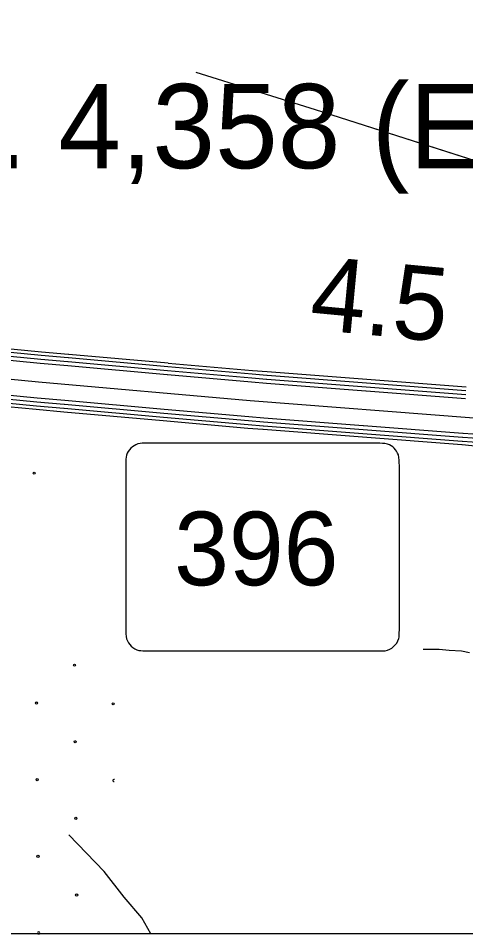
# Model space of a CAD drawing. Extents: x 1577619 to 1828281, y 483481 to 598136.
# Drawn here: x 1689672 to 1691916, y 508120 to 512713 of the extents above; entities that cross this region are included whole.
import ezdxf

# ---------------------------------------------------------------- set-up
doc = ezdxf.new("R2010")
doc.units = 0
for name, color, linetype in [('DESIGN - EROSION CONTROL - Devices', 7, 'Continuous'), ('DESIGN - ROW - Slope Lines', 7, 'Continuous'), ('DESIGN - SHEET - Linework', 7, 'Continuous'), ('DESIGN - TRAFFIC CONTROL PERMANENT - Signalization', 7, 'Continuous'), ('DESIGN - TRANSPORTATION - Text', 7, 'Continuous'), ('SURVEY - CENTERLINE - Preliminary Text', 7, 'Continuous'), ('SURVEY - DRAINAGE - Natural Features', 7, 'Continuous'), ('SURVEY - VEGETATION - Features with Text', 7, 'Continuous')]:
    doc.layers.add(name, color=color, linetype=linetype)

msp = doc.modelspace()

# ---------------------------------------------------------------- linework, layer by layer
at = {"layer": 'DESIGN - EROSION CONTROL - Devices'}
msp.add_line((1689770.1, 508119.9), (1689777.7, 508119.9), dxfattribs=at)
for centre in [(1689751.5, 510430.9), (1689953.1, 509467.7), (1689762.7, 509277.3), (1690147.3, 509273.5), (1689956.8, 509083.1), (1689766.4, 508892.7), (1689960.6, 508698.6), (1689770.2, 508508.2), (1689964.3, 508314)]:
    msp.add_circle(centre, 5.28, dxfattribs=at)
for centre, start, end in [((1690151, 508889), 61.0095, 287.6299), ((1689773.9, 508123.6), 315.4751, 224.5249)]:
    msp.add_arc(centre, 5.28, start, end, dxfattribs=at)
at = {"layer": 'DESIGN - ROW - Slope Lines'}
for p, q in [((1691472.6, 510580.9), (1690315.7, 510580.8)), ((1690210.5, 510479.6), (1690210.5, 509647.9)), ((1691583.4, 509649.2), (1691583.4, 510469.2)), ((1690316.9, 509538.5), (1691473.5, 509538.5))]:
    msp.add_line(p, q, dxfattribs=at)
for centre, radius, start, end in [((1690299.4, 510492), 89.8, 108.3711, 161.4494), ((1690306.4, 510420.8), 160.4, 86.6485, 102.7002), ((1691481.7, 510382.8), 198.2, 77.6972, 92.6427), ((1691493.9, 510491.4), 90.3, 20.2626, 70.5274), ((1690423.3, 510480.8), 212.8, 169.2361, 180.3208), ((1691329.8, 510473.5), 253.6, 359.0166, 11.1674), ((1690484.6, 509647.1), 274.1, 179.8527, 189.8963), ((1690636.3, 509654), 947.1, 357.7373, 359.7127), ((1690301.2, 509629.1), 91.3, 198.5723, 254.4317), ((1691495, 509626.9), 89.4, 280.9255, 342.7445), ((1691514, 509618.1), 68.6, 345.0701, 358.7436), ((1690320.8, 509900.9), 362.4, 263.0109, 269.3986), ((1691484, 510073.3), 534.8, 268.8795, 272.9943)]:
    msp.add_arc(centre, radius, start, end, dxfattribs=at)
at = {"layer": 'DESIGN - SHEET - Linework'}
msp.add_lwpolyline([(1669171.5, 526510.7), (1695618, 526510.7), (1695618, 508119.9), (1669171.5, 508119.9)], close=True, dxfattribs=at)
at = {"layer": 'DESIGN - TRANSPORTATION - Text'}
for points in [[(1691935, 509528.5), (1691895.1, 509536.8), (1691833.2, 509541.1), (1691783.4, 509545.4), (1691713.5, 509545.8), (1691703, 509546.2)], [(1690337.1, 508119.9), (1690291.8, 508199.9), (1690202.7, 508302.7), (1690101.9, 508431.7), (1689925.6, 508615.3)]]:
    msp.add_lwpolyline(points, dxfattribs=at)
at = {"layer": 'SURVEY - CENTERLINE - Preliminary Text'}
for points in [[(1687408, 512747), (1687465.3, 512524.3), (1687524.5, 512313.8), (1687573.8, 512143.4), (1687617.3, 512027.1), (1687670.8, 511904.8), (1687744.1, 511756.3), (1687841.5, 511605.8), (1687980.8, 511451), (1688138.1, 511304.3), (1688221.2, 511244.5), (1688321.5, 511183.4), (1688510.1, 511088), (1688653.6, 511032.8), (1688789.6, 510996.6), (1688914.8, 510972), (1689773.3, 510889.3), (1690834.2, 510795), (1691957, 510708.4), (1692968.1, 510642.4), (1694238.8, 510549.2), (1695351.7, 510466.7), (1695618, 510446.8)], [(1689425.6, 511057.4), (1689785.6, 511022.7), (1689922.4, 511010.5)], [(1689427.3, 511074.8), (1689787.3, 511040.1), (1689924, 511028)], [(1689422.7, 511017.2), (1689781.9, 510982.6), (1689919.8, 510970.3)], [(1689423.7, 511037.5), (1689783.8, 511002.8), (1689920.6, 510990.6)], [(1689923.3, 511010.5), (1690421.4, 510966.2)], [(1689924.9, 511027.9), (1690422.9, 510983.6)], [(1689920.7, 510970.3), (1690418.7, 510926)], [(1689921.5, 510990.5), (1690419.6, 510946.3)], [(1690422.3, 510966.1), (1690845.2, 510928.5), (1690918.8, 510922.8)], [(1690423.8, 510983.5), (1690846.7, 510945.9), (1690920.1, 510940.3)], [(1690419.6, 510925.9), (1690841.9, 510888.4), (1690916.6, 510882.6)], [(1690420.5, 510946.2), (1690843.6, 510908.6), (1690917.2, 510902.9)], [(1690919.7, 510922.8), (1691418.2, 510884.3)], [(1690921, 510940.2), (1691419.5, 510901.8)], [(1690917.5, 510882.5), (1691416, 510844.1)], [(1690918.1, 510902.8), (1691416.7, 510864.4)], [(1691417.6, 510864.3), (1691916.1, 510825.9)], [(1691419.1, 510884.3), (1691917.6, 510845.8)], [(1691420.4, 510901.7), (1691919, 510863.3)], [(1689404, 510823.4), (1689764, 510788.7), (1689902.5, 510776.4)], [(1689405.9, 510843.6), (1689765.8, 510808.9), (1689904.3, 510796.6)], [(1691416.9, 510844), (1691915.4, 510805.6)], [(1689400.4, 510786), (1689760.5, 510751.4), (1689899.2, 510739)], [(1689402.1, 510803.5), (1689762.1, 510768.8), (1689900.7, 510756.5)], [(1689903.4, 510776.3), (1690401.4, 510732)], [(1689905.2, 510796.5), (1690403.2, 510752.2)], [(1689900.1, 510738.9), (1690398.1, 510694.7)], [(1689901.6, 510756.4), (1690399.7, 510712.1)], [(1690402.3, 510731.9), (1690825.8, 510694.3), (1690901.6, 510688.4)], [(1690404.1, 510752.1), (1690827.5, 510714.5), (1690903.2, 510708.7)], [(1690399, 510694.6), (1690822.7, 510656.9), (1690898.7, 510651.1)], [(1690400.6, 510712), (1690824.2, 510674.4), (1690900.1, 510668.5)], [(1690902.5, 510688.4), (1691401, 510650)], [(1690904.1, 510708.6), (1691402.6, 510670.2)], [(1690899.6, 510651), (1691398.2, 510612.6)], [(1690901, 510668.4), (1691399.5, 510630)], [(1691401.9, 510649.9), (1691900.5, 510611.5)], [(1691403.5, 510670.1), (1691902, 510631.7)], [(1691902.9, 510631.6), (1691951.3, 510627.9), (1692402.7, 510598.4)], [(1691399.1, 510612.5), (1691897.6, 510574.1)], [(1691400.4, 510629.9), (1691898.9, 510591.5)], [(1691899.8, 510591.4), (1691948.4, 510587.7), (1692400.1, 510558.2)], [(1691901.4, 510611.4), (1691949.9, 510607.6), (1692401.4, 510578.1)], [(1691898.5, 510574), (1691947.2, 510570.2), (1692399, 510540.7)]]:
    msp.add_lwpolyline(points, dxfattribs=at)
at = {"layer": 'SURVEY - DRAINAGE - Natural Features'}
for points in [[(1696135.5, 510664.2), (1691163.2, 512253.5), (1690563.6, 512440.6)], [(1696135.5, 510664.2), (1691163.2, 512253.5), (1690563.6, 512440.6)], [(1695618, 510829.6), (1691163.2, 512253.5), (1690563.6, 512440.6)], [(1695618, 510829.6), (1691163.2, 512253.5), (1690563.6, 512440.6)]]:
    msp.add_lwpolyline(points, dxfattribs=at)

# ---------------------------------------------------------------- texts
at = {"layer": 'DESIGN - ROW - Slope Lines'}
msp.add_text('396', height=369.61, rotation=0.0012, dxfattribs=at).set_placement((1690453.3, 509868.1))
at = {"layer": 'DESIGN - TRAFFIC CONTROL PERMANENT - Signalization'}
msp.add_text('4.5', height=369.99, rotation=354.5852, dxfattribs=at).set_placement((1691127.1, 511153.3))
at = {"layer": 'SURVEY - VEGETATION - Features with Text'}
msp.add_text('POP. 4,358 (EST.)', height=422.99, rotation=0, dxfattribs=at).set_placement((1688363.4, 511960.7))

doc.saveas('drawing.dxf')
